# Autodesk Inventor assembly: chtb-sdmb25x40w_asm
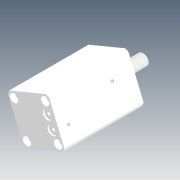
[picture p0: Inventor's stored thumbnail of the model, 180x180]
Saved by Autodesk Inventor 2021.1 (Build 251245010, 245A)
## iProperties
Company: Microsoft
Created: 2018-05
Part Number: chtb-sdmb25x40w_asm
Description: STEP AP214
Document SubType Name: Assembly
Designer: user
Title: chtb-sdmb25x40w_asm.STEP
Author: Windows
Revision Number: ÈÎºÎ
Sending System: SolidWorks 2015
Preprocessor: SwSTEP 2.0
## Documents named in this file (4)
- D:\Vault_2016\Projekty\Clamptek\Hydraulic\CHTB\CHTB-25\Inventor\chtb-sdmb25x40w\chtb-sdmb25x40w_asm.iam
- D:\Vault_2016\Projekty\Clamptek\Hydraulic\CHTB\CHTB-25\Inventor\chtb-sdmb25x40w\CHTB-25QG.ipt
- D:\Vault_2016\Projekty\Clamptek\Hydraulic\CHTB\CHTB-25\Inventor\chtb-sdmb25x40w\CHTB-SDMB25X40NBT.ipt
- D:\Vault_2016\Projekty\Clamptek\Hydraulic\CHTB\CHTB-25\Inventor\chtb-sdmb25x40w\CHTB-SDMB25X40WHSG.ipt
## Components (3 placed, 3 different names)
1. CHTB-25QG_1
2. CHTB-SDMB25X40NBT_2
3. CHTB-SDMB25X40WHSG_3
